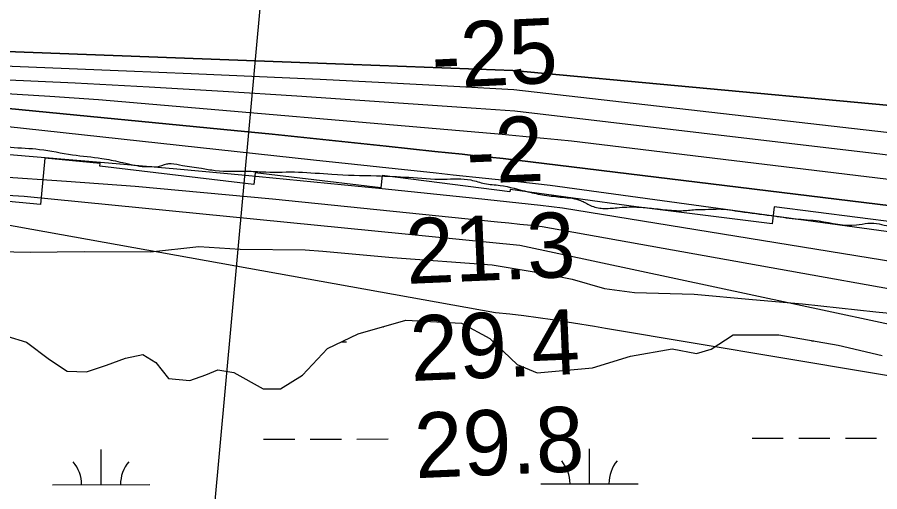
# Model space of a CAD drawing. Extents: x 3329332 to 3367211, y 631066 to 656469.
# Drawn here: x 3334750 to 3335636, y 645540 to 646028 of the extents above; entities that cross this region are included whole.
import ezdxf

# ---------------------------------------------------------------- set-up
doc = ezdxf.new("R2010")
doc.units = 0
for name, color, linetype in [('V-RIVR-EDGE', 7, 'Continuous'), ('V-RIVR-RANG', 7, 'Continuous'), ('V-RRAP-RVMT', 7, 'Continuous'), ('V-SITE-VEGE', 7, 'Continuous'), ('V-TOPO-DPTH', 7, 'Continuous'), ('V-TOPO-MAJR', 7, 'Continuous'), ('V-TOPO-MINR', 7, 'Continuous'), ('V-TOPO-WATR', 7, 'Continuous'), ('V-WETL-SWMP', 7, 'Continuous')]:
    doc.layers.add(name, color=color, linetype=linetype)

msp = doc.modelspace()

# ---------------------------------------------------------------- linework, layer by layer
at = {"layer": 'V-RIVR-EDGE'}
msp.add_spline([(3333442.63, 645911.21), (3333443.43, 645911.31), (3333470.49, 645916), (3333482.93, 645919.99), (3333490.98, 645923.99), (3333504.54, 645939.67), (3333512.98, 645952.45), (3333516.3, 645963.04), (3333522.53, 645969.97), (3333533.88, 645977.25), (3333548.15, 645980.87), (3333560.21, 645980.84), (3333571.91, 645982.64), (3333587.28, 645987.72), (3333597.53, 645992.81), (3333616.18, 645996.42), (3333639.21, 645996.37), (3333674.3, 645994.82), (3333714.86, 645990.7), (3333740.07, 645986.61), (3333764.56, 645984.36), (3333781.73, 645981.76), (3333808.42, 645979.86), (3333834.37, 645979.8), (3333849.73, 645981.59), (3333869.09, 645977.89), (3333881.87, 645972.01), (3333888.8, 645966.14), (3333898.3, 645962.46), (3333912.92, 645960.96), (3333922.42, 645962.04), (3333935.58, 645959.44), (3333947.27, 645956.13), (3333952.38, 645955.02), (3333959.69, 645955), (3333977.96, 645953.49), (3333998.43, 645951.25), (3334021.45, 645948.63), (3334032.06, 645949.7), (3334046.32, 645952.59), (3334053.27, 645952.57), (3334068.24, 645947.42), (3334077.36, 645941.55), (3334084.3, 645936.05), (3334087.95, 645936.04), (3334096.72, 645936.02), (3334111.34, 645931.59), (3334132.52, 645922.4), (3334152.6, 645915.04), (3334162.46, 645912.09), (3334179.64, 645908.76), (3334201.2, 645906.51), (3334214.35, 645904.65), (3334226.41, 645900.97), (3334234.81, 645897.29), (3334247.23, 645893.24), (3334259.65, 645893.58), (3334272.46, 645898.66), (3334281.98, 645904.85), (3334290.77, 645912.14), (3334296.63, 645913.95), (3334306.86, 645913.56), (3334322.2, 645909.5), (3334339.73, 645902.52), (3334352.51, 645895.54), (3334363.83, 645892.22), (3334378.45, 645892.18), (3334390.52, 645894.71), (3334400.05, 645902.37), (3334412.87, 645913.67), (3334428.97, 645919.48), (3334443.96, 645920.17), (3334461.87, 645918.66), (3334476.85, 645916.8), (3334491.46, 645912.38), (3334506.06, 645905.03), (3334526.89, 645899.86), (3334543.7, 645899.45), (3334561.62, 645901.6), (3334587.22, 645907.39), (3334601.48, 645909.55), (3334620.5, 645911.69), (3334653.03, 645910.15), (3334662.53, 645908.66), (3334700.53, 645901.62), (3334716.24, 645898.29), (3334742.91, 645894.57), (3334772.52, 645892.31), (3334806.5, 645886.74), (3334836.46, 645883.01), (3334855.46, 645879.31), (3334878.12, 645874.86), (3334891.28, 645874.47), (3334893.1, 645874.46), (3334903.35, 645877.36), (3334907.73, 645877.72), (3334919.43, 645875.86), (3334938.79, 645872.89), (3334953.04, 645870.66), (3334987.77, 645869.84), (3335004.95, 645869.07), (3335038.58, 645868.98), (3335072.93, 645866.71), (3335118.62, 645865.13), (3335151.89, 645863.59), (3335187.7, 645861.67), (3335215.85, 645860.87), (3335229.73, 645857.18), (3335245.81, 645855.31), (3335274.31, 645848.66), (3335291.48, 645845.33), (3335309.75, 645843.09), (3335319.98, 645841.97), (3335328.39, 645839.76), (3335338.61, 645834.61), (3335351.4, 645831.66), (3335366.02, 645832.35), (3335386.13, 645833.03), (3335403.67, 645831.53), (3335421.94, 645829.65), (3335432.18, 645829.26), (3335446.44, 645830.32), (3335459.96, 645830.66), (3335470.2, 645831), (3335492.86, 645828.38), (3335524.28, 645824.28), (3335549.13, 645820.93), (3335573.62, 645818.68), (3335611.99, 645814.56), (3335623.69, 645816.36), (3335629.91, 645816.35), (3335650.73, 645811.91), (3335671.56, 645807.47), (3335694.94, 645803.39), (3335701.16, 645804.47), (3335711.77, 645807.74), (3335718.36, 645812.47), (3335722.02, 645812.83), (3335723.84, 645809.9), (3335723.83, 645808.44), (3335724.19, 645804.78), (3335726.75, 645803.68), (3335734.05, 645801.47), (3335746.47, 645796.68), (3335751.95, 645796.67), (3335763.65, 645796.64), (3335781.2, 645796.96), (3335792.53, 645797.3), (3335799.84, 645796.55), (3335804.22, 645793.25), (3335811.53, 645792.5), (3335818.84, 645793.58), (3335828.34, 645791), (3335845.51, 645788.4)], degree=3, dxfattribs=at)
at = {"layer": 'V-RIVR-RANG'}
msp.add_line((3334926.93, 645248.62), (3335038.5, 646463.51), dxfattribs=at)
at = {"layer": 'V-RRAP-RVMT'}
for p, q in [((3334778.03, 645883.37), (3334773.64, 645835.68)), ((3334834.9, 645877.91), (3334778.03, 645883.37)), ((3334834.54, 645874.96), (3334834.9, 645877.91)), ((3334992.75, 645856.15), (3334834.54, 645874.96)), ((3334994.24, 645868.16), (3334992.75, 645856.15)), ((3335123.14, 645852.92), (3334994.24, 645868.16)), ((3335124.62, 645865.4), (3335123.14, 645852.92)), ((3335255.76, 645848.79), (3335124.62, 645865.4)), ((3334773.64, 645835.68), (3334572.2, 645854.06)), ((3335256.07, 645851.17), (3335255.76, 645848.79)), ((3335385.47, 645833.24), (3335256.07, 645851.17)), ((3335525.28, 645815.84), (3335385.47, 645833.24)), ((3335527.28, 645833.31), (3335525.28, 645815.84)), ((3335655.75, 645816.69), (3335527.28, 645833.31))]:
    msp.add_line(p, q, dxfattribs=at)
at = {"layer": 'V-SITE-VEGE'}
for p, q in [((3334886.44, 645786.99), (3334936.36, 645792.35)), ((3334936.36, 645792.35), (3334978.54, 645789.59)), ((3334691.82, 645787.99), (3334763.01, 645786.75)), ((3334763.01, 645786.75), (3334818.35, 645787.45)), ((3334818.35, 645787.45), (3334886.44, 645786.99)), ((3334978.54, 645789.59), (3335045.48, 645789.13)), ((3335045.48, 645789.13), (3335063.74, 645787.53)), ((3335063.74, 645787.53), (3335135.23, 645781.28)), ((3335135.23, 645781.28), (3335237.76, 645773.43)), ((3335237.76, 645773.43), (3335291.15, 645764.85)), ((3335291.15, 645764.85), (3335319.77, 645759.01)), ((3335319.77, 645759.01), (3335353.04, 645749.3)), ((3335353.04, 645749.3), (3335383.98, 645745.01)), ((3335383.98, 645745.01), (3335445.12, 645743.39)), ((3335445.12, 645743.39), (3335505.09, 645737.9)), ((3335505.09, 645737.9), (3335556.54, 645733.59)), ((3335556.54, 645733.59), (3335631.99, 645725.38)), ((3335631.99, 645725.38), (3335693.11, 645719.11))]:
    msp.add_line(p, q, dxfattribs=at)
at = {"layer": 'V-TOPO-DPTH'}
for points in [[(3336159.2, 645883.45), (3336067.9, 645894.28), (3336044.33, 645897.37), (3336020.83, 645900.83), (3335997.42, 645904.86), (3335258.96, 645973.38), (3335222.5, 645974.82), (3335186.03, 645976.19), (3335149.56, 645977.53), (3335113.08, 645978.88), (3335076.61, 645980.24), (3334628.61, 645997.1)], [(3336159.2, 645883.45), (3336067.9, 645894.28), (3336044.33, 645897.37), (3336020.83, 645900.83), (3335997.42, 645904.86), (3335258.96, 645973.38), (3335222.5, 645974.82), (3335186.03, 645976.19), (3335149.56, 645977.53), (3335113.08, 645978.88), (3335076.61, 645980.24), (3334628.61, 645997.1)], [(3334733.15, 645963.97), (3334809.17, 645960.55), (3334885.17, 645956.71), (3334961.13, 645952.25), (3335037.07, 645947.36), (3335221.24, 645934.75), (3335241.04, 645933.37), (3335260.84, 645931.94), (3335734.74, 645876.13), (3335773.05, 645871.03), (3335849.77, 645861.64), (3335868.48, 645859.48), (3335897.51, 645856.07), (3335926.53, 645852.58), (3335955.54, 645848.99), (3335984.54, 645845.32), (3336080.36, 645833.02), (3336157.18, 645822.57)], [(3334733.15, 645963.97), (3334809.17, 645960.55), (3334885.17, 645956.71), (3334961.13, 645952.25), (3335037.07, 645947.36), (3335221.24, 645934.75), (3335241.04, 645933.37), (3335260.84, 645931.94), (3335734.74, 645876.13), (3335773.05, 645871.03), (3335849.77, 645861.64), (3335868.48, 645859.48), (3335897.51, 645856.07), (3335926.53, 645852.58), (3335955.54, 645848.99), (3335984.54, 645845.32), (3336080.36, 645833.02), (3336157.18, 645822.57)], [(3335919.88, 645801.11), (3335263.14, 645881.26), (3335249.1, 645882.77), (3335235.05, 645884.27), (3335221.01, 645885.75), (3335206.96, 645887.24), (3335192.92, 645888.75), (3335178.88, 645890.26), (3335128.88, 645895.66), (3335089.83, 645899.82), (3335050.78, 645903.89), (3335011.71, 645907.85), (3334972.64, 645911.73), (3334740.77, 645934.4)], [(3335919.88, 645801.11), (3335263.14, 645881.26), (3335249.1, 645882.77), (3335235.05, 645884.27), (3335221.01, 645885.75), (3335206.96, 645887.24), (3335192.92, 645888.75), (3335178.88, 645890.26), (3335128.88, 645895.66), (3335089.83, 645899.82), (3335050.78, 645903.89), (3335011.71, 645907.85), (3334972.64, 645911.73), (3334740.77, 645934.4)], [(3334631.38, 645896.43), (3334843.31, 645878.48), (3334913.68, 645872.32), (3334984.02, 645865.89), (3335054.33, 645859.06), (3335124.61, 645851.97), (3335220.45, 645842.01), (3335242.79, 645839.67), (3335265.12, 645837.28), (3335287.45, 645834.83), (3335309.77, 645832.35), (3335803.26, 645752.02), (3335862.77, 645741.88), (3335893.85, 645736.63), (3335924.94, 645731.45), (3335956.05, 645726.39), (3335987.17, 645721.39), (3336008.01, 645718.08), (3336049.56, 645711.43), (3336091.09, 645704.72), (3336132.61, 645697.91), (3336174.12, 645691.04)]]:
    msp.add_lwpolyline(points, dxfattribs=at)
at = {"layer": 'V-TOPO-MAJR'}
msp.add_lwpolyline([(3334628.96, 645834.7), (3335241.04, 645724.67), (3335255.69, 645723.2), (3335270.31, 645721.54), (3335284.89, 645719.6), (3335299.46, 645717.46), (3335342.95, 645710.66), (3335354.07, 645708.64), (3335902.67, 645616.53), (3335913, 645615.73), (3335923.31, 645614.84), (3335933.62, 645613.82), (3335943.92, 645612.73), (3336615.67, 645452.42)], dxfattribs=at)
at = {"layer": 'V-TOPO-MINR'}
for points in [[(3334628.61, 645997.1), (3335076.61, 645980.24), (3335113.08, 645978.88), (3335149.56, 645977.53), (3335186.03, 645976.19), (3335222.5, 645974.82), (3335258.96, 645973.38), (3335997.42, 645904.86), (3336020.83, 645900.83), (3336044.33, 645897.37), (3336067.9, 645894.28), (3336159.2, 645883.45)], [(3334634.65, 645982.22), (3334861.93, 645973.17), (3334928.27, 645970.41), (3335060.92, 645964.34), (3335127.23, 645961.03), (3335198.08, 645957.37), (3335228.96, 645955.72), (3335259.83, 645953.99), (3335846.29, 645886.72), (3335861.42, 645884.53), (3335876.59, 645882.58), (3335891.77, 645880.78), (3335894.13, 645880.51), (3335910.5, 645878.68), (3335926.88, 645876.85), (3335943.26, 645874.99), (3335959.63, 645873.13), (3336264.62, 645838.34)], [(3334733.15, 645963.97), (3334809.17, 645960.55), (3334885.17, 645956.71), (3334961.13, 645952.25), (3335037.07, 645947.36), (3335221.24, 645934.75), (3335241.04, 645933.37), (3335260.84, 645931.94), (3335734.74, 645876.13), (3335773.05, 645871.03), (3335849.77, 645861.64), (3335868.48, 645859.48), (3335897.51, 645856.07), (3335926.53, 645852.58), (3335955.54, 645848.99), (3335984.54, 645845.32), (3336080.36, 645833.02), (3336157.18, 645822.57)], [(3334732.86, 645950), (3334783.07, 645947.14), (3334833.23, 645943.59), (3335247.87, 645907.79), (3335254.93, 645907.16), (3335262, 645906.53), (3335269.06, 645905.87), (3335276.12, 645905.2), (3335290.64, 645903.81), (3335304.96, 645902.39), (3335319.27, 645900.92), (3335684.61, 645856.91), (3335745.01, 645849.55), (3335805.41, 645842.2), (3335893.25, 645831.52), (3335909.73, 645829.48), (3335926.2, 645827.39), (3335942.66, 645825.24), (3335959.11, 645823.04), (3336010.35, 645816.09), (3336052.39, 645810.15), (3336094.37, 645803.9), (3336136.29, 645797.18), (3336178.15, 645790.14)], [(3334658.47, 645924.65), (3335054.03, 645881.54), (3335096.04, 645877.02), (3335138.06, 645872.55), (3335180.09, 645868.12), (3335197.64, 645866.28), (3335230.89, 645862.75), (3335264.13, 645859.17), (3335297.36, 645855.51), (3335840.13, 645781.01), (3335857.8, 645777.81), (3335875.48, 645774.62), (3335897.15, 645770.72), (3335911.27, 645768.2), (3335925.39, 645765.72), (3335939.52, 645763.29), (3335953.66, 645760.89), (3336079.58, 645739.77), (3336156.69, 645726.88)], [(3334631.38, 645896.43), (3334843.31, 645878.48), (3334913.68, 645872.32), (3334984.02, 645865.89), (3335054.33, 645859.06), (3335124.61, 645851.97), (3335220.45, 645842.01), (3335242.79, 645839.67), (3335265.12, 645837.28), (3335287.45, 645834.83), (3335309.77, 645832.35), (3335803.26, 645752.02), (3335862.77, 645741.88), (3335893.85, 645736.63), (3335924.94, 645731.45), (3335956.05, 645726.39), (3335987.17, 645721.39), (3336008.01, 645718.08), (3336049.56, 645711.43), (3336091.09, 645704.72), (3336132.61, 645697.91), (3336174.12, 645691.04)], [(3334729.69, 645864.35), (3334800.32, 645859.75), (3334870.9, 645854.53), (3335011.87, 645841.62), (3335243.2, 645817.87), (3335254.66, 645816.68), (3335266.12, 645815.46), (3335277.57, 645814.22), (3335289.02, 645812.95), (3335912.79, 645701.18), (3335918.63, 645700.25), (3335924.48, 645699.34), (3335930.33, 645698.44), (3335936.19, 645697.56), (3335942.04, 645696.66), (3335947.89, 645695.74), (3335953.73, 645694.79), (3335959.57, 645693.8), (3335964.34, 645692.98), (3335972.56, 645691.55), (3335980.77, 645690.11), (3335988.98, 645688.63), (3335997.18, 645687.13), (3336206.3, 645648.49)], [(3334715.18, 645846.51), (3334756.86, 645844.1), (3335265.9, 645793.84), (3335952.01, 645647.06), (3335980.22, 645643.06), (3336075.06, 645629.16), (3336133.76, 645619.78), (3336192.26, 645609.4)]]:
    msp.add_lwpolyline(points, dxfattribs=at)
at = {"layer": 'V-TOPO-WATR'}
msp.add_lwpolyline([(3334740.77, 645934.4), (3334972.64, 645911.73), (3335011.71, 645907.85), (3335050.78, 645903.89), (3335089.83, 645899.82), (3335128.88, 645895.66), (3335178.88, 645890.26), (3335192.92, 645888.75), (3335206.96, 645887.24), (3335221.01, 645885.75), (3335235.05, 645884.27), (3335249.1, 645882.77), (3335263.14, 645881.26), (3335919.88, 645801.11)], dxfattribs=at)
at = {"layer": 'V-WETL-SWMP'}
for p, q in [((3335099.79, 645702.61), (3335148.98, 645716.68)), ((3335148.98, 645716.68), (3335205.99, 645713.47)), ((3335205.99, 645713.47), (3335235.26, 645697.75)), ((3335068.39, 645687.48), (3335099.79, 645702.61)), ((3335125.53, 645709.98), (3335125.92, 645709.98)), ((3334738.87, 645700.41), (3334759.26, 645694.11)), ((3334759.26, 645694.11), (3334782.78, 645676.3)), ((3335082.88, 645694.46), (3335087.95, 645694.47)), ((3335235.26, 645697.75), (3335263.48, 645671.04)), ((3335462.79, 645687.02), (3335485.3, 645701.64)), ((3335485.3, 645701.64), (3335532.37, 645701.59)), ((3335532.37, 645701.59), (3335593.04, 645691.06)), ((3335565.86, 645695.38), (3335568.13, 645695.38)), ((3335042.73, 645660.31), (3335068.39, 645687.48)), ((3335379.61, 645679.8), (3335422.51, 645687.07)), ((3335422.51, 645687.07), (3335447.61, 645682.33)), ((3335447.61, 645682.33), (3335462.79, 645687.02)), ((3335593.04, 645691.06), (3335638.53, 645680.55)), ((3334782.78, 645676.3), (3334801.07, 645664.25)), ((3334841.35, 645670.48), (3334860.72, 645677.78)), ((3334860.72, 645677.78), (3334878.51, 645681.42)), ((3334878.51, 645681.42), (3334892.1, 645673.04)), ((3335340.89, 645667.81), (3335379.61, 645679.8)), ((3334820.95, 645663.7), (3334841.35, 645670.48)), ((3334892.1, 645673.04), (3334905.15, 645656.81)), ((3335263.48, 645671.04), (3335283.87, 645662.65)), ((3335283.87, 645662.65), (3335340.89, 645667.81)), ((3334801.07, 645664.25), (3334820.95, 645663.7)), ((3334927.12, 645654.69), (3334943.34, 645660.42)), ((3334943.34, 645660.42), (3334955.9, 645665.64)), ((3334955.9, 645665.64), (3334972.12, 645663)), ((3334972.12, 645663), (3335002.43, 645646.23)), ((3335020.22, 645646.22), (3335042.73, 645660.31)), ((3334905.15, 645656.81), (3334927.12, 645654.69)), ((3335002.43, 645646.23), (3335020.22, 645646.22)), ((3335002.73, 645594.31), (3335034.73, 645594.37)), ((3335050.73, 645594.4), (3335082.73, 645594.46)), ((3335098.73, 645594.49), (3335130.73, 645594.55)), ((3335504.64, 645595.26), (3335536.64, 645595.32)), ((3335552.64, 645595.35), (3335584.64, 645595.41)), ((3335600.64, 645595.44), (3335632.64, 645595.5)), ((3334835.76, 645547.57), (3334835.69, 645583.57)), ((3335337.66, 645548.52), (3335337.6, 645584.52)), ((3334785.76, 645547.47), (3334885.76, 645547.66)), ((3335287.66, 645548.42), (3335387.66, 645548.61))]:
    msp.add_line(p, q, dxfattribs=at)
for centre, start, end in [((3334780.51, 645547.94), 359.33649, 40.88015), ((3334891, 645548.15), 139.33647, 180.88013), ((3335282.42, 645548.89), 359.33649, 40.88015), ((3335392.91, 645549.09), 139.33647, 180.88013)]:
    msp.add_arc(centre, 35.25, start, end, dxfattribs=at)

# ---------------------------------------------------------------- texts
at = {"layer": 'V-RIVR-RANG'}
for s, rotation, p in [('-25', 2.73622, (3335176.72, 645954.86)), ('-2', 2.44833, (3335212.16, 645856.7)), ('21.3', 2.44833, (3335150.01, 645753.95)), ('29.4', 2.44833, (3335154.54, 645654.06)), ('29.8', 2.44833, (3335159.06, 645554.16))]:
    msp.add_text(s, height=67, rotation=rotation, dxfattribs=at).set_placement(p)

doc.saveas('drawing.dxf')
